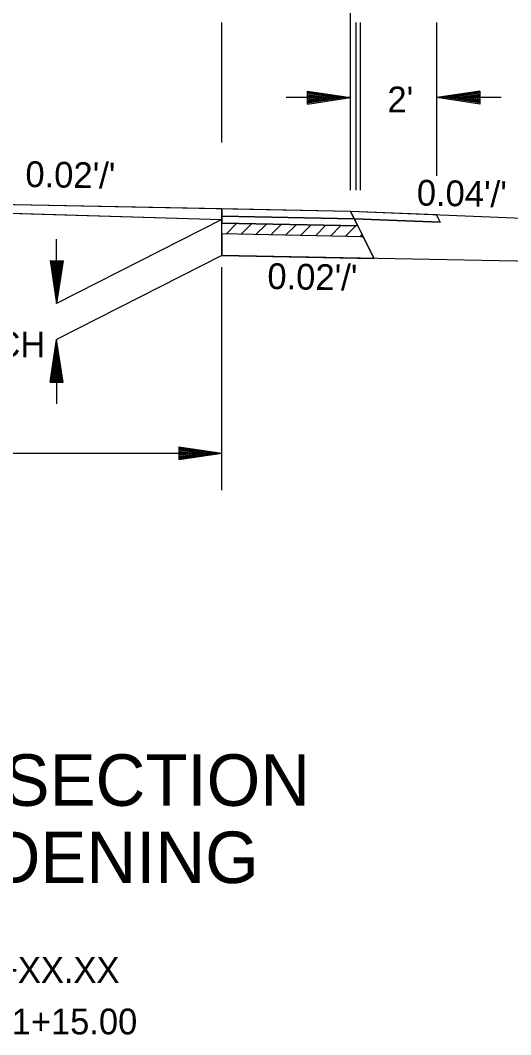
# Model space of a CAD drawing. Extents: x 138 to 3619, y -519 to 1449.
# Drawn here: x 641.1 to 755.2, y -519.1 to -282.8 of the extents above; entities that cross this region are included whole.
import ezdxf

# ---------------------------------------------------------------- set-up
doc = ezdxf.new("R2010")
doc.units = 0
for name, color, linetype in [('R_Annotation', 7, 'Continuous'), ('R_Dimension', 7, 'Continuous'), ('R_No Plot', 7, 'Continuous')]:
    doc.layers.add(name, color=color, linetype=linetype)

msp = doc.modelspace()

# ---------------------------------------------------------------- linework, layer by layer
at = {"layer": 'R_Annotation'}
for p, q in [((718, -327.31), (608, -325.11)), ((688, -337.55), (688, -326.71)), ((718.84, -329), (688, -328.38)), ((758, -328.91), (718, -327.31)), ((738, -328.11), (738.85, -329.82)), ((719.68, -330.68), (688, -330.05)), ((738.85, -329.82), (718.85, -329.02)), ((720.95, -333.21), (688, -332.55)), ((801.63, -339.82), (688, -337.55))]:
    msp.add_line(p, q, dxfattribs=at)
at = {"layer": 'R_Dimension'}
for p, q in [((718, -322.31), (718, -255.78)), ((688, -311.21), (688, -283.28)), ((719.27, -322.31), (719.27, -283.28)), ((720.32, -322.31), (720.32, -283.28)), ((738.02, -319.04), (738.02, -283.28)), ((708, -299.28), (718, -300.78)), ((708, -302.28), (708, -299.28)), ((708, -299.53), (716.33, -300.78)), ((708, -299.79), (714.61, -300.78)), ((708, -300.04), (712.95, -300.78)), ((748.02, -299.28), (738.02, -300.78)), ((748.02, -299.53), (739.69, -300.78)), ((748.02, -299.79), (741.41, -300.78)), ((748.02, -300.04), (743.07, -300.78)), ((748.02, -299.28), (748.02, -302.28)), ((718, -300.78), (703, -300.78)), ((708, -300.29), (711.25, -300.78)), ((708, -300.55), (709.58, -300.78)), ((708, -302.28), (718, -300.78)), ((708, -301.27), (711.25, -300.78)), ((708, -301.78), (714.61, -300.78)), ((708, -302.03), (716.33, -300.78)), ((708, -301.53), (712.95, -300.78)), ((708, -301.02), (709.58, -300.78)), ((748.02, -302.28), (738.02, -300.78)), ((753.02, -300.78), (738.02, -300.78)), ((748.02, -302.03), (739.69, -300.78)), ((748.02, -301.78), (741.41, -300.78)), ((748.02, -301.53), (743.07, -300.78)), ((748.02, -300.3), (744.77, -300.78)), ((748.02, -301.27), (744.77, -300.78)), ((748.02, -300.55), (746.44, -300.78)), ((748.02, -301.02), (746.44, -300.78)), ((688, -326.71), (608, -325.11)), ((608, -326.78), (688, -329.21)), ((718, -327.31), (688, -326.71)), ((688, -329.21), (688, -326.71)), ((688, -326.71), (688, -328.38)), ((718, -327.31), (688, -326.71)), ((688, -328.38), (718.84, -329)), ((688, -328.39), (718.85, -329.02)), ((688, -328.39), (688, -330.06)), ((718.85, -329.02), (688, -328.39)), ((718, -327.31), (718.85, -329.02)), ((738, -328.11), (718, -327.31)), ((718.85, -329.02), (718, -327.31)), ((718.84, -329), (718, -327.31)), ((738.85, -329.82), (738, -328.11)), ((688, -329.21), (649.59, -348.76)), ((688, -330.05), (719.68, -330.68)), ((688, -330.06), (719.68, -330.68)), ((689.02, -332.57), (691.47, -330.12)), ((692.48, -332.64), (694.93, -330.19)), ((695.95, -332.71), (698.4, -330.26)), ((699.41, -332.78), (701.87, -330.32)), ((702.88, -332.85), (705.33, -330.39)), ((706.35, -332.91), (708.8, -330.46)), ((709.81, -332.98), (712.26, -330.53)), ((713.28, -333.05), (715.73, -330.6)), ((716.74, -333.12), (719.2, -330.67)), ((718.85, -329.02), (738.85, -329.82)), ((719.68, -330.68), (718.85, -329.02)), ((719.68, -330.68), (718.85, -329.02)), ((720.21, -333.19), (720.7, -332.71)), ((649.59, -348.76), (649.59, -333.76)), ((688, -337.55), (649.59, -357.1)), ((648.1, -338.76), (649.59, -348.76)), ((648.1, -338.76), (651.1, -338.77)), ((648.35, -338.76), (649.6, -347.09)), ((648.61, -338.76), (649.6, -345.37)), ((648.86, -338.76), (649.6, -343.71)), ((649.12, -338.76), (649.6, -342.01)), ((649.37, -338.76), (649.6, -340.34)), ((651.1, -338.77), (649.59, -348.76)), ((650.09, -338.76), (649.6, -342.01)), ((650.35, -338.76), (649.6, -343.71)), ((649.84, -338.76), (649.6, -340.34)), ((650.6, -338.77), (649.6, -345.37)), ((650.85, -338.77), (649.6, -347.09)), ((688, -392.25), (688, -340.25)), ((648.1, -367.1), (649.59, -357.1)), ((648.35, -367.1), (649.6, -358.77)), ((651.1, -367.1), (649.59, -357.1)), ((649.59, -357.1), (649.59, -372.1)), ((650.85, -367.1), (649.6, -358.77)), ((648.61, -367.1), (649.6, -360.49)), ((650.6, -367.1), (649.6, -360.49)), ((648.86, -367.1), (649.6, -362.15)), ((649.12, -367.1), (649.6, -363.85)), ((650.35, -367.1), (649.6, -362.15)), ((650.09, -367.1), (649.6, -363.85)), ((649.37, -367.1), (649.6, -365.52)), ((649.84, -367.1), (649.6, -365.52)), ((648.1, -367.1), (651.1, -367.1)), ((678.02, -382.11), (688.02, -383.61)), ((678.02, -382.11), (678.02, -385.11)), ((678.02, -382.36), (686.35, -383.61)), ((678.02, -382.62), (684.63, -383.61)), ((498, -383.61), (688, -383.61)), ((678.02, -382.87), (682.96, -383.61)), ((678.02, -383.13), (681.27, -383.61)), ((678.02, -383.38), (679.6, -383.61)), ((678.02, -385.11), (688.02, -383.61)), ((678.02, -384.1), (681.27, -383.61)), ((678.02, -384.61), (684.63, -383.61)), ((678.02, -384.86), (686.35, -383.61)), ((678.02, -384.36), (682.96, -383.61)), ((678.02, -383.85), (679.6, -383.61))]:
    msp.add_line(p, q, dxfattribs=at)
for points in [[(498, -330.65), (608, -326.78), (687.95, -329.21)], [(718.85, -329.02), (688, -328.39)]]:
    msp.add_lwpolyline(points, dxfattribs=at)
for points in [[(688, -334.84), (688.02, -334.84), (688.03, -334.84), (688.05, -334.84)], [(720.64, -333.22), (720.75, -333.22), (720.86, -333.23), (720.96, -333.24)]]:
    msp.add_open_spline(points, degree=3, dxfattribs=at)
at = {"layer": 'R_No Plot'}
msp.add_line((718, -327.31), (723.47, -338.26), dxfattribs=at)
msp.add_lwpolyline([(720.95, -333.21), (688, -332.55), (688, -337.55), (723.47, -338.26)], close=True, dxfattribs=at)

# ---------------------------------------------------------------- texts
at = {"layer": 'R_Annotation'}
for s, height, p in [("2'", 6, (726.57, -304.22)), ('NOTCH', 6, (618.43, -361.27)), ('HWY. 90 - TANGENT SECTION', 12, (477.65, -465.75)), ('NOTCH AND WIDENING', 12, (514.79, -483.75)), ('STA. 110+00.00 TO STA. XX+XX.XX', 6, (531.32, -506.98)), ('STA. XX+XX.XX TO STA. 111+15.00', 6, (535.46, -518.98))]:
    msp.add_text(s, height=height, dxfattribs=at).set_placement(p)
for s, p in [("0.02'/'", (642.29, -321.59)), ("0.04'/'", (733.35, -325.92)), ("0.02'/'", (698.59, -345.35))]:
    msp.add_text(s, height=6, rotation=358.9387, dxfattribs=at).set_placement(p)

doc.saveas('drawing.dxf')
